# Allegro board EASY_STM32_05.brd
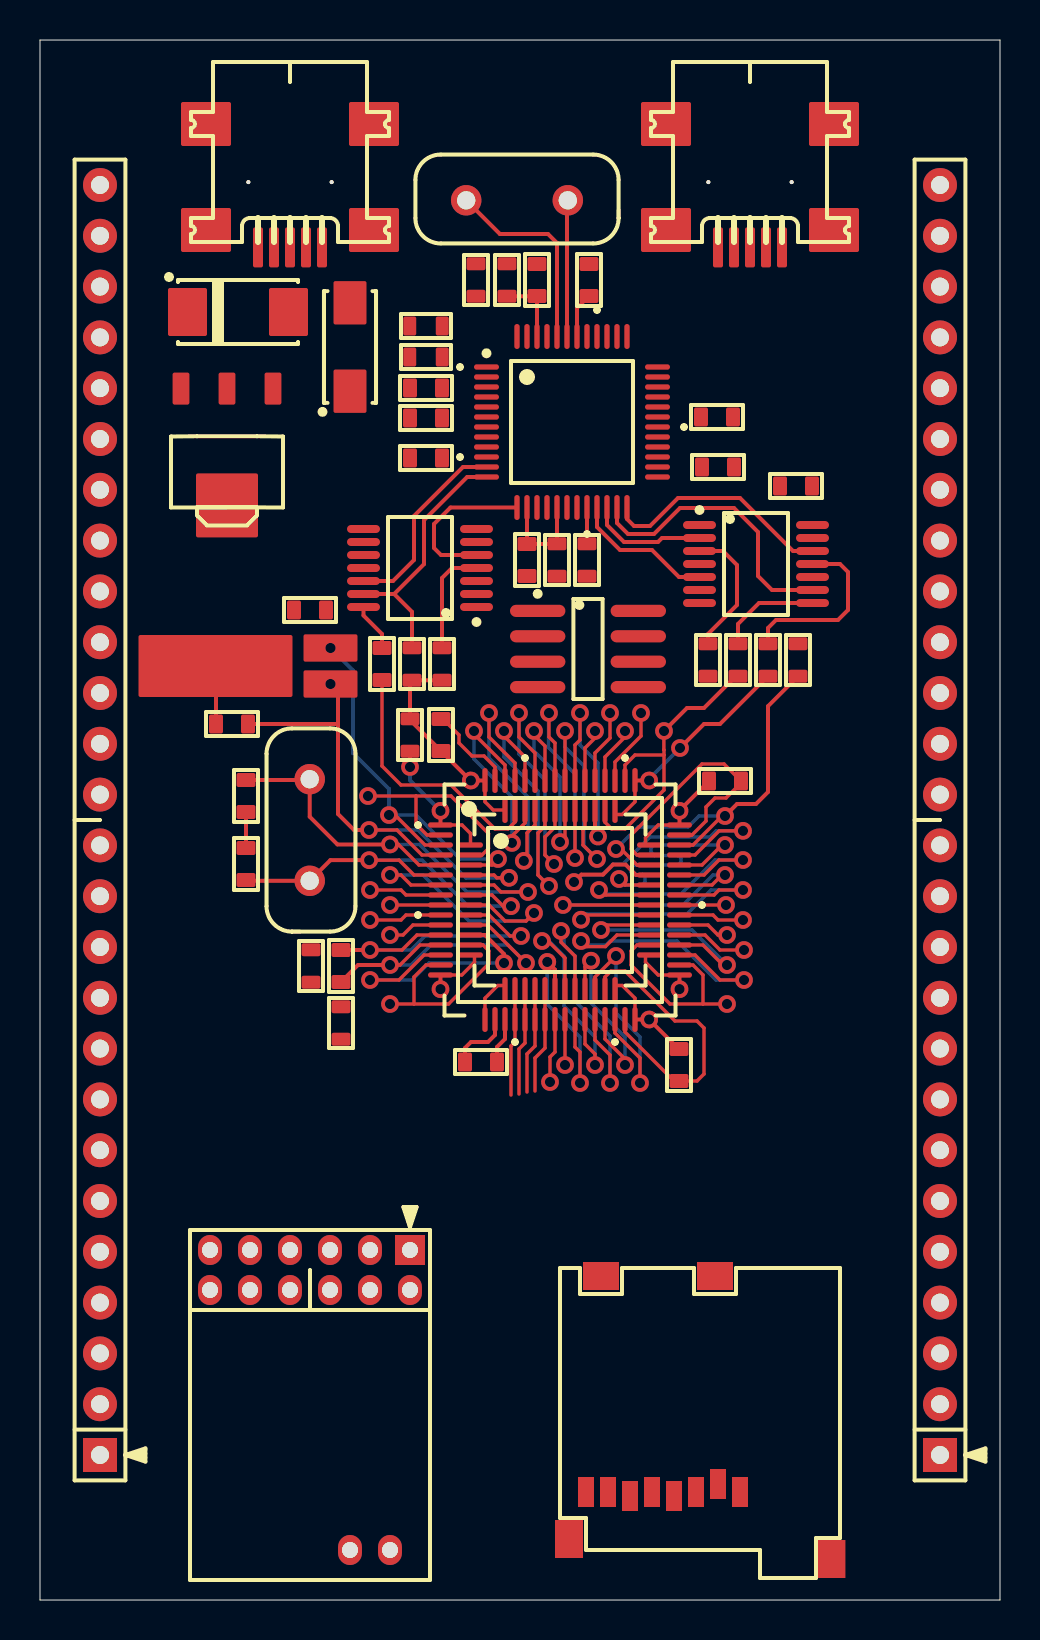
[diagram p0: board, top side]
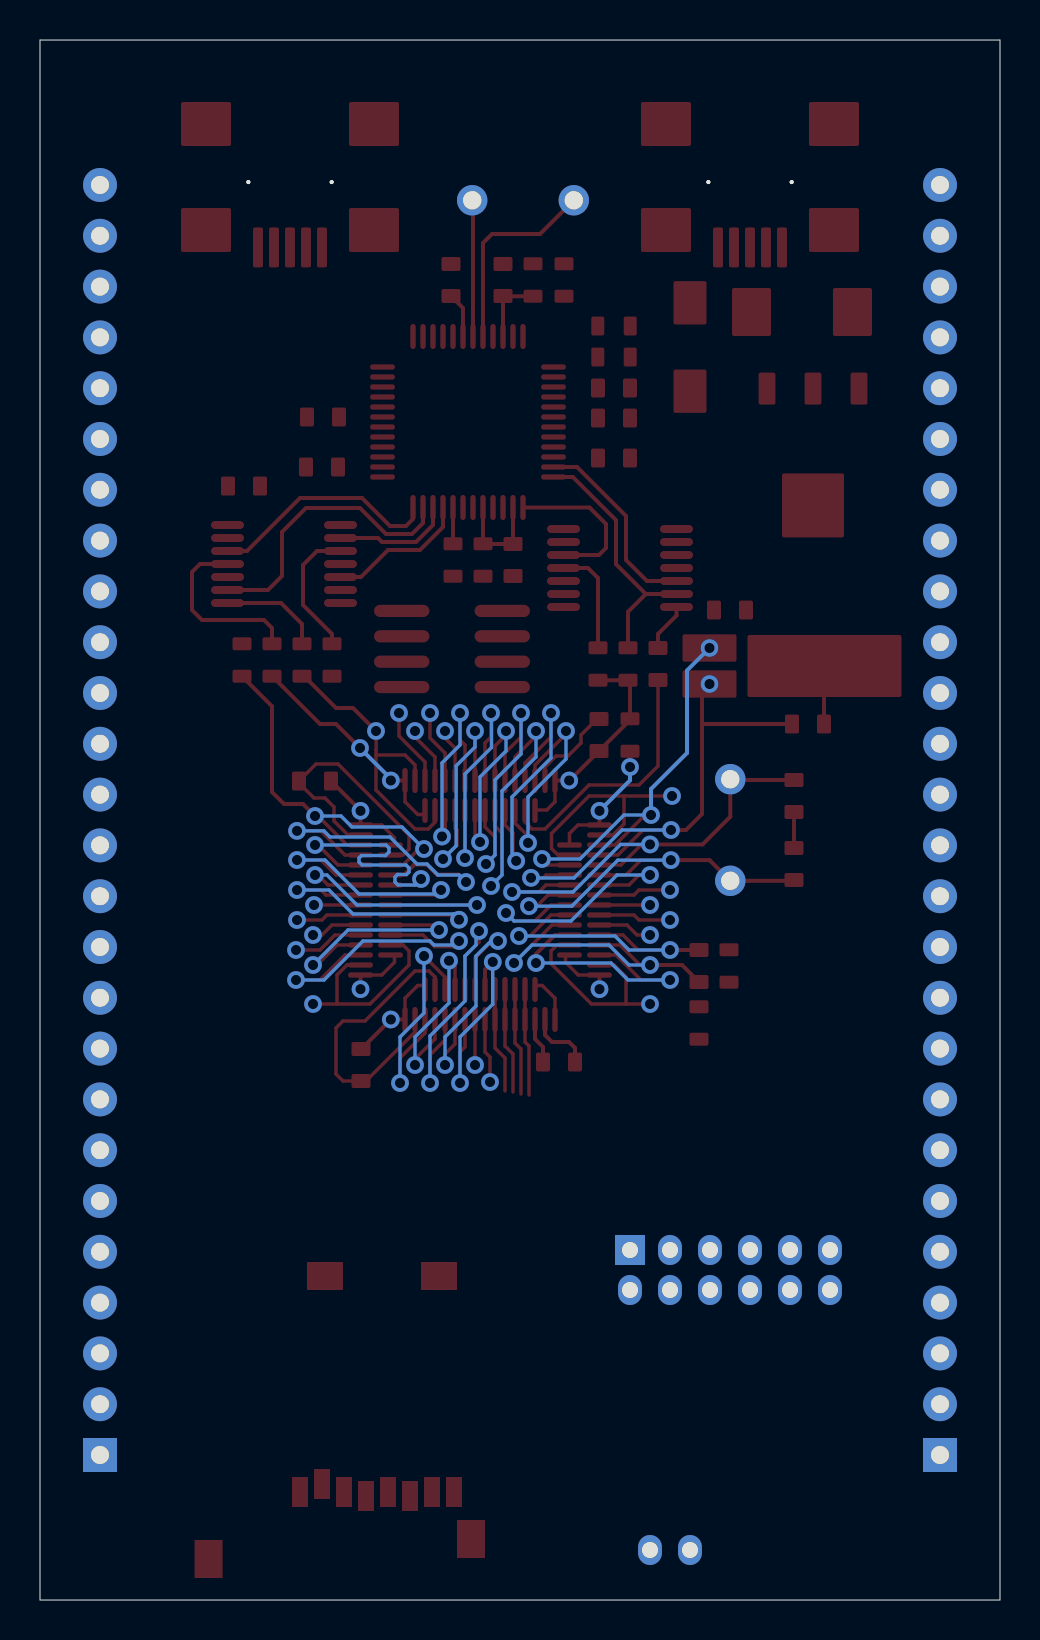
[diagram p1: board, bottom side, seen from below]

Outline 48 x 78 mm; copper layers: TOP, BOTTOM. Coordinates in mm from the lower left corner of the outline.
Outline path: 0,78 0,0 48,0 48,78 0,78

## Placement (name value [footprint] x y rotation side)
C1  22pF  [CAP0603_B]  10.3 40.2 270 top
C2  22p  [CAP0603_B]  10.3 36.8 90 top
C3  15p  [CAP0603_B]  9.6 43.8 180 top
C4  15p  [CAP0603_B]  13.5 49.5 180 top
C5  100n  [CAP0603_B]  15.05 31.7 90 top
C6  100n  [CAP0603_B]  31.95 26.75 270 top
C7  100n  [CAP0603_B]  34.25 40.95 0 top
C8  100n  [CAP0603_B]  20.05 43.25 90 top
C9  100n  [CAP0603_B]  22.05 26.9 180 top
C11  100n  [CAP0603_B]  19.3 60.6 180 top
C12  100n  [CAP0603_B]  27.45 66 90 top
C14  100n  [CAP0603_B]  19.3 57.1 180 top
C15  100n  [CAP0603_B]  24.35 52 270 top
C16  100n  [CAP0603_B]  33.9 56.65 0 top
C17  100n  [CAP0603_B]  33.85 59.15 0 top
C18  100n  [CAP0603_B]  24.85 66 90 top
C19  100n  [CAP0603_B]  19.3 59.1 180 top
C23  220uF  [CAP220UF]  9.9 64.4 0 top
C45  100nF  [CAP0603_B]  37.8 55.7 180 top
C46  100nF  [CAP0603_B]  17.1 46.8 270 top
D2  1N5819  [SS14]  15.5 62.65 90 top
J1  USB_MB  [HIROSE-US60-MB-5ST]  12.5 76.9 180 top
J*  USB_MB  [unnamed#2]  35.5 76.9 180 top
NOREF  -  []  0 -2 0 top
NOREF#2  -  []  50 0 90 top
R1  0R  [RES0603_B]  18.5 43.25 90 top
R2  0R  [RES0603_B]  15.05 28.85 270 top
R3  0R  [RES0603_B]  13.55 31.7 270 top
R4  470R  [RES0603_B]  23.35 66 270 top
R5  4K7  [RES0603_B]  19.3 63.7 0 top
R6  10K  [RES0603_B]  19.3 62.15 180 top
R7  10K  [RES0603_B]  27.35 52 270 top
R13  1K5  [RES0603_B]  21.8 66 90 top
R14  100K  [RES0603_B]  25.85 52 270 top
R35  100R  [RES0603_B]  33.4 47 270 top
R36  100R  [RES0603_B]  37.9 47 270 top
R37  100R  [RES0603_B]  34.9 47 270 top
R38  100R  [RES0603_B]  36.4 47 270 top
R39  100K  [RES0603_B]  18.6 46.8 90 top
R40  100K  [RES0603_B]  20.1 46.8 90 top
REF  val  [unnamed#3]  45 7.25 90 top
REF#2  val  [unnamed#4]  18.5 17.5 180 top
U1  STM32F103RCT6  [LQFP64_MODIFIED]  26 35 0 top
U2  STM32F100  [LQFP48L_MODIFIED]  26 35 0 top
U3  FT2232D  [LQFP48L]  26.6 58.9 0 top
U4  AT93C46-10SI-2.7  [SOIC8S1JEDECM]  27.4 47.55 270 top
U5  74LVC125A  [TSOP65P640X120-14]  35.8 51.8 270 top
U6  74LVC125A  [TSOP65P640X120-14]  19 51.6 90 top
U7  LD1117-3V3  [SOT-223]  9.35 57.38 180 top
U10  MICRO_SD  [MICRO_SD_PUSH]  40 16.6 180 top
UNK*  val  [unnamed#3]  3 7.25 90 top
Y1  8M  [XTAL_DIP]  13.49 35.96 90 top
Y2  32.768KHz  [RTC-CRYSTAL]  10.53 46.7 90 top
Y3  6M  [XTAL_DIP]  26.39 69.99 180 top

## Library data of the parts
C1-C9 = C1005_0: User Part Number: pn; Tolerance: RichardLC
C11 C12 C14-C19 = CAP NP_0: User Part Number: pn; Tolerance: RichardLC
C23 = CAPACITOR POL: User Part Number: pn; Tolerance: RichardLC
C45 C46 = C1005_5: User Part Number: pn; Tolerance: RichardLC
D2 = DIODE SCHOTTKY_1: User Part Number: pn; Tolerance: RichardLC
J1 = CON9: User Part Number: pn; Tolerance: RichardLC
J* UNK* = -: Tolerance: RichardLC; User Part Number: pn
R1-R7 R13 R14 R35-R40 = R_0: User Part Number: pn; Tolerance: RichardLC
REF REF#2 = -: User Part Number: pn; Tolerance: RichardLC
U1 = STM32F103RCT6_2: User Part Number: pn; Tolerance: RichardLC
U2 = STM32F100_1: User Part Number: pn; Tolerance: RichardLC
U3 = FT2232D_0: User Part Number: pn; Tolerance: RichardLC
U4 = 93C46_2: User Part Number: pn; Tolerance: RichardLC
U5 U6 = 74HC125/LCC_0: User Part Number: pn; Tolerance: RichardLC
U7 = LD1117: User Part Number: pn; Tolerance: RichardLC
U10 = MOLEX_uSD_0: User Part Number: pn; Tolerance: RichardLC
Y1 Y3 = ZTB: Tolerance: ***; User Part Number: ***
Y2 = ZTA_0: User Part Number: pn; Tolerance: RichardLC

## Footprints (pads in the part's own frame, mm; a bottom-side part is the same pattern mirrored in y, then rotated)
CAP220UF
  custom 0.487x0.487 smd: 1(-2.525,0) 2(2.525,0)
CAP0603_B
  custom 0.175x0.175 smd: 1(-0.8,0) 2(0.8,0)
HIROSE-US60-MB-5ST
  round 0.2 hole 0.9 unplated: (-2.083,6.005) (2.083,6.005)
  custom 0.125x0.125 smd: 1(-1.6,9.271) 2(-0.8,9.271) 3(0,9.271) 4(0.8,9.271) 5(1.6,9.271)
  custom 0.55x0.55 smd: 6(-4.2,3.1) 7(4.2,3.1) 8(-4.2,8.4) 9(4.2,8.4)
LQFP48L
  oval 1.25x0.27 smd: 1(-4.275,2.75) 2(-4.275,2.25) 3(-4.275,1.75) 4(-4.275,1.25) 5(-4.275,0.75) 6(-4.275,0.25) 7(-4.275,-0.25) 8(-4.275,-0.75) 9(-4.275,-1.25) 10(-4.275,-1.75) 11(-4.275,-2.25) 12(-4.275,-2.75) 25(4.275,-2.75) 26(4.275,-2.25) 27(4.275,-1.75) 28(4.275,-1.25) 29(4.275,-0.75) 30(4.275,-0.25) 31(4.275,0.25) 32(4.275,0.75) 33(4.275,1.25) 34(4.275,1.75) 35(4.275,2.25) 36(4.275,2.75)
  oval 0.27x1.25 smd: 13(-2.75,-4.275) 14(-2.25,-4.275) 15(-1.75,-4.275) 16(-1.25,-4.275) 17(-0.75,-4.275) 18(-0.25,-4.275) 19(0.25,-4.275) 20(0.75,-4.275) 21(1.25,-4.275) 22(1.75,-4.275) 23(2.25,-4.275) 24(2.75,-4.275) 37(2.75,4.275) 38(2.25,4.275) 39(1.75,4.275) 40(1.25,4.275) 41(0.75,4.275) 42(0.25,4.275) 43(-0.25,4.275) 44(-0.75,4.275) 45(-1.25,4.275) 46(-1.75,4.275) 47(-2.25,4.275) 48(-2.75,4.275)
LQFP48L_MODIFIED
  oval 1.25x0.27 smd: 1(-4.475,2.75) 2(-4.475,2.25) 3(-4.475,1.75) 4(-4.475,1.25) 5(-4.475,0.75) 6(-4.475,0.25) 7(-4.475,-0.25) 8(-4.475,-0.75) 9(-4.475,-1.25) 10(-4.475,-1.75) 11(-4.475,-2.25) 12(-4.475,-2.75) 25(4.475,-2.75) 26(4.475,-2.25) 27(4.475,-1.75) 28(4.475,-1.25) 29(4.475,-0.75) 30(4.475,-0.25) 31(4.475,0.25) 32(4.475,0.75) 33(4.475,1.25) 34(4.475,1.75) 35(4.475,2.25) 36(4.475,2.75)
  oval 0.27x1.25 smd: 13(-2.75,-4.475) 14(-2.25,-4.475) 15(-1.75,-4.475) 16(-1.25,-4.475) 17(-0.75,-4.475) 18(-0.25,-4.475) 19(0.25,-4.475) 20(0.75,-4.475) 21(1.25,-4.475) 22(1.75,-4.475) 23(2.25,-4.475) 24(2.75,-4.475) 37(2.75,4.475) 38(2.25,4.475) 39(1.75,4.475) 40(1.25,4.475) 41(0.75,4.475) 42(0.25,4.475) 43(-0.25,4.475) 44(-0.75,4.475) 45(-1.25,4.475) 46(-1.75,4.475) 47(-2.25,4.475) 48(-2.75,4.475)
LQFP64_MODIFIED
  oval 1.25x0.27 smd: 1(-5.975,3.75) 2(-5.975,3.25) 3(-5.975,2.75) 4(-5.975,2.25) 5(-5.975,1.75) 6(-5.975,1.25) 7(-5.975,0.75) 8(-5.975,0.25) 9(-5.975,-0.25) 10(-5.975,-0.75) 11(-5.975,-1.25) 12(-5.975,-1.75) 13(-5.975,-2.25) 14(-5.975,-2.75) 15(-5.975,-3.25) 16(-5.975,-3.75) 33(5.975,-3.75) 34(5.975,-3.25) 35(5.975,-2.75) 36(5.975,-2.25) 37(5.975,-1.75) 38(5.975,-1.25) 39(5.975,-0.75) 40(5.975,-0.25) 41(5.975,0.25) 42(5.975,0.75) 43(5.975,1.25) 44(5.975,1.75) 45(5.975,2.25) 46(5.975,2.75) 47(5.975,3.25) 48(5.975,3.75)
  oval 0.27x1.25 smd: 17(-3.75,-5.975) 18(-3.25,-5.975) 19(-2.75,-5.975) 20(-2.25,-5.975) 21(-1.75,-5.975) 22(-1.25,-5.975) 23(-0.75,-5.975) 24(-0.25,-5.975) 25(0.25,-5.975) 26(0.75,-5.975) 27(1.25,-5.975) 28(1.75,-5.975) 29(2.25,-5.975) 30(2.75,-5.975) 31(3.25,-5.975) 32(3.75,-5.975) 49(3.75,5.975) 50(3.25,5.975) 51(2.75,5.975) 52(2.25,5.975) 53(1.75,5.975) 54(1.25,5.975) 55(0.75,5.975) 56(0.25,5.975) 57(-0.25,5.975) 58(-0.75,5.975) 59(-1.25,5.975) 60(-1.75,5.975) 61(-2.25,5.975) 62(-2.75,5.975) 63(-3.25,5.975) 64(-3.75,5.975)
MICRO_SD_PUSH
  rect 0.8x1.5 smd: 1(5,11.2) 2(6.1,10.8) 3(7.2,11.2) 4(8.3,11.4) 5(9.4,11.2) 6(10.5,11.4) 7(11.6,11.2) 8(12.7,11.2)
  rect 1.4x1.9 smd: G1(0.43,14.55) G2(13.55,13.55)
  rect 1.8x1.4 smd: S1(6.25,0.4) S2(11.95,0.4)
RES0603_B
  custom 0.163x0.163 smd: 1(-0.812,0) 2(0.812,0)
RTC-CRYSTAL
  custom 0.343x0.343 smd: 1(-0.9,-4) 2(0.9,-4)
  custom 0.775x0.775 smd: 3(0,1.75)
SOIC8S1JEDECM
  oval 0.61x2.77 smd: 1(-1.905,-2.515) 2(-0.635,-2.515) 3(0.635,-2.515) 4(1.905,-2.515) 5(1.905,2.515) 6(0.635,2.515) 7(-0.635,2.515) 8(-1.905,2.515)
SOT-223
  custom 0.21x0.21 smd: 1(-2.3,-3.195) 2(0,-3.195) 3(2.3,-3.195)
  custom 0.775x0.775 smd: 4(0,2.645)
SS14
  custom 0.412x0.412 smd: A(2.21,0) C(-2.21,0)
TSOP65P640X120-14
  oval 0.4x1.65 smd: 1(-1.95,-2.825) 2(-1.3,-2.825) 3(-0.65,-2.825) 4(0,-2.825) 5(0.65,-2.825) 6(1.3,-2.825) 7(1.95,-2.825) 8(1.95,2.825) 9(1.3,2.825) 10(0.65,2.825) 11(0,2.825) 12(-0.65,2.825) 13(-1.3,2.825) 14(-1.95,2.825)
unnamed#2
  round 0.2 hole 0.9 unplated: (-2.083,6.005) (2.083,6.005)
  custom 0.125x0.125 smd: 1(-1.6,9.271) 2(-0.8,9.271) 3(0,9.271) 4(0.8,9.271) 5(1.6,9.271)
  custom 0.55x0.55 smd: 6(-4.2,3.1) 7(4.2,3.1) 8(-4.2,8.4) 9(4.2,8.4)
unnamed#3
  rect 1.7x1.7 hole 0.9: 1(0,0)
  round 1.7 hole 0.9: 2(2.54,0) 3(5.08,0) 4(7.62,0) 5(10.16,0) 6(12.7,0) 7(15.24,0) 8(17.78,0) 9(20.32,0) 10(22.86,0) 11(25.4,0) 12(27.94,0) 13(30.48,0) 14(33.02,0) 15(35.56,0) 16(38.1,0) 17(40.64,0) 18(43.18,0) 19(45.72,0) 20(48.26,0) 21(50.8,0) 22(53.34,0) 23(55.88,0) 24(58.42,0) 25(60.96,0) 26(63.5,0)
unnamed#4
  rect 1.5x1.5 hole 0.8: 1(0,0)
  oval 1.194x1.499 hole 0.8: 2(0,2) 3(2,0) 4(2,2) 5(4,0) 6(4,2) 7(6,0) 8(6,2) 9(8,0) 10(8,2) 11(10,0) 12(10,2) 13(1,15) 14(3,15)
XTAL_DIP
  round 1.524 hole 0.914: 1(0,0) 2(5.08,0)

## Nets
+3V3: C6.1 C7.1 C8.1 C9.1 C14.1 C15.1 C16.1 C17.1 C45.1 C46.1 R1.2 R2.2 R14.1 R39.1 R40.1 U1.19(VDD_4) U1.32(VDD_1) U1.48(VDD_2) U1.64(VDD_3) U2.24(VDD_1) U2.36(VDD_2) U2.48(VDD_3) U3.10(SI/WUA) U3.14(VCCIOA) U3.17(ADBUS6) U3.26(SI/WUB) U3.31(VCCIOB) U5.14(VCC) U6.14(VCC) U7.2(VOUT) U7.4(SH) U10.4(VDD)
+5V: C11.1 C12.1 C23.1 D2.C R4.1 U3.3(VCC1) U3.42(VCC2) U4.8(VCC) U7.3(VIN)
GND: C1.2 C2.2 C3.2 C4.2 C6.2 C7.2 C8.2 C9.2 C11.2 C12.2 C14.2 C15.2 C16.2 C17.2 C18.2 C19.2 C23.2 C45.2 C46.2 J1.5 J1.6 J1.7 J1.8 J1.9 R3.2 R6.2 R7.2 R14.2 U1.18(VSS_4) U1.31(VSS_1) U1.47(VSS_2) U1.63(VSS_3) U2.23(VSS_1) U2.35(VSS_2) U2.47(VSS_3) U3.9(GND1) U3.18(GND2) U3.25(GND3) U3.34(GND4) U3.45(AGND) U3.47(TEST) U4.5(GND) U4.7(NC) U5.7(GND) U6.1(O\E\1\) U6.2(A1) U6.7(GND) U6.9(A3) U6.10(O\E\3\) U7.1(GND) U10.6(VSS) Y2.3
VBAT: R1.1 U1.1(VBAT) U2.1(VBAT)
VDDA: C5.1 R2.1 U1.13(VDDA) U2.9(VDDA)
VSSA: C5.2 R3.1 U1.12(VSSA) U2.8(VSSA)
BOOT0: U1.60(BOOT0) U2.44(BOOT0)
EECK: U3.1(EESK) U4.2(CLK)
EECS: U3.48(EECS) U4.1(CS)
EEDA: U3.2(EEDATA) U4.3(DI)
JT_SRSTN: U3.16(ADBUS7)
JTG_SELN: U5.1(O\E\1\) U5.4(O\E\2\) U5.10(O\E\3\) U5.13(O\E\4\)
NRST: U1.7(NRST) U2.7(NRST)
OSC32_IN: C4.1 U1.3(PC14/OSC32_IN) U2.3(PC14/OSC32_IN) Y2.2
OSC32_OUT: C3.1 U1.4(PC15/OSC32/OUT) U2.4(PC15/OSC32_OUT) Y2.1
OSC_IN: C1.1 U1.5(PD0/OSC_IN) U2.5(PD0/OSC_IN) Y1.2
OSC_OUT: C2.1 U1.6(PD1/OSC_OUT) U2.6(PD1/OSC_OUT) Y1.1
PA0: U1.14(PA0-WKUP) U2.10(PA0/WKUP)
PA1: U1.15(PA1) U2.11(PA1)
PA2: U1.16(PA2) U2.12(PA2)
PA3: U1.17(PA3) U2.13(PA3)
PA4: U1.20(PA4) U2.14(PA4)
PA5: U1.21(PA5) U2.15(PA5)
PA6: U1.22(PA6) U2.16(PA6)
PA7: U1.23(PA7) U2.17(PA7)
PA8: U1.41(PA8) U2.29(PA8)
PA9: U1.42(PA9) U2.30(PA9)
PA10: U1.43(PA10) U2.31(PA10)
PA11: U1.44(PA11) U2.32(PA11)
PA12: U1.45(PA12) U2.33(PA12)
PA13: R36.2 U1.46(PA13) U2.34(PA13)
PA14: R38.2 U1.49(PA14) U2.37(PA14)
PA15: R37.2 U1.50(PA15) U2.38(PA15)
PB0: U1.26(PB0) U2.18(PB0)
PB1: U1.27(PB1) U2.19(PB1)
PB2: U1.28(PB2/BOOT1) U2.20(PB2)
PB3: R35.2 U1.55(PB3) U2.39(PB3)
PB4: U1.56(PB4) U2.40(PB4)
PB5: U1.57(PB5) U2.41(PB5)
PB6: U1.58(PB6) U2.42(PB6)
PB7: U1.59(PB7) U2.43(PB7)
PB8: U1.61(PB8) U2.45(PB8)
PB9: U1.62(PB9) U2.46(PB9)
PB10: U1.29(PB10) U2.21(PB10)
PB11: U1.30(PB11) U2.22(PB11)
PB12: U1.33(PB12) U2.25(PB12)
PB13: U1.34(PB13) U2.26(PB13)
PB14: U1.35(PB14) U2.27(PB14)
PB15: U1.36(PB15) U2.28(PB15)
PC0: U1.8(PC0)
PC1: U1.9(PC1)
PC2: U1.10(PC2)
PC3: U1.11(PC3)
PC4: U1.24(PC4)
PC5: U1.25(PC5)
PC6: U1.37(PC6)
PC7: U1.38(PC7)
PC8: U1.39(PC8)
PC9: U1.40(PC9)
PC10: U1.51(PC10)
PC11: U1.52(PC11)
PC12: U1.53(PC12)
PC13: U1.2(PC13/TAMPER/RTC) U2.2(PC13/TAMPER/RTC)
PD2: U1.54(PD2)
RXD: U3.39(BDBUS1)
SRST: U3.11(ACBUS3) U6.12(A4)
SRST_OE: R39.2 U3.12(ACBUS2) U6.13(O\E\4\)
TRST: U3.13(ACBUS1) U6.5(A2)
TRST_OE: R40.2 U3.15(ACBUS0) U6.4(O\E\2\)
TXD: U3.40(BDBUS0)
USB_CLK: U3.24(ADBUS0) U5.12(A4)
USB_TDI: U3.23(ADBUS1) U5.9(A3)
USB_TDO: U3.22(ADBUS2) U5.2(A1)
USB_TMS: U3.21(ADBUS3) U5.5(A2)
N50123: J1.3 R13.1 U3.7(USBDP)
N50127: C18.1 R4.2 U3.46(AVCC)
N50535: R7.1 U3.20(ADBUS4)
N50793: U3.43(XTIN) Y3.1
N50801: U3.44(XTOUT) Y3.2
N51025: J1.1
N51029: D2.A R5.1
N51319: R13.2 U3.5(R\S\T\O\U\T\)
N51335: J1.2 U3.8(USBDM)
N51347: R5.2 R6.1 U3.4(R\E\S\E\T\)
N51363: C19.1 U3.6(3V3OUT)
N51511: U4.4(DO)
N70187: U10.7(DAT0/DO)
N70219: U10.5(CLK)
N70227: U10.2(CD/C\S\/DAT3)
N70305: U10.S2
N70345: U10.G2
N70603: U10.8(DAT1/RSV)
N14914218: U10.3(CMD/DI)
N14919452: R35.1 U5.3(Y1)
N14919456: R36.1 U5.6(Y2)
N14919460: R37.1 U5.8(Y3)
N14919464: R38.1 U5.11(Y4)
N14919761: U10.1(DAT2/NC)
N14928576: U6.6(Y2)
N14928580: U6.11(Y4)

Pads without a net: J1 4; J* 1 2 3 4 5 6 7 8 9; REF 1 2 3 4 5 6 7 8 9 10 11 12 13 14 15 16 17 18 19 20 21 22 23 24 25 26; REF#2 1 2 3 4 5 6 7 8 9 10 11 12 13 14; U3 19 27 28 29 30 32 33 35 36 37 38 41; U4 6; U6 3 8; U10 G1 S1; UNK* 1 2 3 4 5 6 7 8 9 10 11 12 13 14 15 16 17 18 19 20 21 22 23 24 25 26

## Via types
v1: diameter 0.889, hole 0.508, TOP to BOTTOM, 87 vias

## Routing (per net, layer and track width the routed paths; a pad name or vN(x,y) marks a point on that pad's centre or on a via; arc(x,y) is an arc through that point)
+3V3: length 30.9
  TOP w0.175: U1.48 30.91,38.75 30.27,38.11 30.27,37.75 ; U1.32 29.75,30.09 29.11,30.73 28.75,30.73 ; 23.25,39.5 22.66,39.5 22.25,39.91 U1.64
  TOP w0.2: U1.64 v1(21.54,40.98) 21.52,40.98 C8.1 18.5,44 R1.2 18.5,45.89 R39.1 R40.1 ; U3.17 R14.1 25.84,52.8 C15.1 U3.14 ; 31.93,27.55 v1(30.46,29.02) U1.32 ; C9.1 22.85,27.65 23.25,28.05 U1.19 ; C46.1 17.1,48.3 16.18,49.23 U6.14 ; C7.1 31.98,39.48 v1(31.98,39.46) U1.48
+5V: length 2.3
  TOP w0.2: 26.85,63.17 26.85,64.6 C12.1
GND: length 54
  TOP w0.175: 28.25,30.73 28.25,31.15 28.55,31.45 29.25,31.45 31.75,28.95 32.85,28.95 33.2,28.6 33.2,26.3 32.85,25.95 C6.2 31.7,25.95 29.25,28.4 U1.31 ; U2.35 29.85,37.25 29.55,37.55 29.55,38.25 33.1,41.8 34.2,41.8 C7.2 35.05,40.85 34.3,40.1 33.75,40.1 33.3,39.65 33.3,38.95 32.6,38.25 U1.47 ; C46.2 17.1,41.7 18.05,40.75 20.55,40.75 22.75,38.55 23.4,38.55 23.75,38.9 U2.47 ; U1.63 22.75,41.65 22.2,42.2 21.6,42.2 20.95,42.85 20.95,43.25 20.15,44.05 C8.2
  TOP w0.2: C9.2 21.25,27.6 21.55,27.9 22.4,27.9 22.75,28.25 U1.18 ; Y2.3 8.8,46.67 C3.2 ; C2.2 C1.2
VBAT: length 6.6
  TOP w0.175: U1.1 21.1,38.75 21.52,38.33 U2.1
  TOP w0.2: U1.1 v1(20.02,39.46) ; R1.1 v1(18.5,41.65)
  BOTTOM w0.2: v1(20.02,39.46) 18.5,40.98 v1(18.5,41.65)
VDDA: length 16.9
  TOP w0.175: v1(17.5,31.75) 18,31.75 19,32.75 U1.13 ; U2.9 22.4,33.75 v1(24.3,31.85)
  TOP w0.2: C5.1 15.9,31.75 v1(17.5,31.75)
  BOTTOM w0.175: v1(24.3,31.85) 23.4,32.75 19.55,32.75 18.55,31.75 v1(17.5,31.75)
VSSA: length 16.1
  TOP w0.175: U2.8 22.45,34.25 23.5,33.2 v1(24.05,33.2) ; U1.12 18.85,33.25 18.1,32.5 v1(16.5,32.5)
  TOP w0.2: v1(16.5,32.5) C5.2
  BOTTOM w0.175: v1(24.05,33.2) 19.25,33.2 18.55,32.5 v1(16.5,32.5)
BOOT0: length 15.7
  TOP w0.175: v1(25.45,35.7) 24.9,36.25 24.9,38.35 25.25,38.7 U2.44 ; v1(23.2,43.45) 23.2,43.2 24.25,42.15 U1.60
  BOTTOM w0.175: v1(23.2,43.45) 23.2,42.15 24.9,40.45 24.9,36.25 v1(25.45,35.7)
NRST: length 14.7
  TOP w0.175: U1.7 18.55,35.75 18.05,36.25 v1(17.5,36.25) ; U2.7 22.45,34.75 23.25,33.95 24.3,33.95 v1(24.7,34.35)
  BOTTOM w0.175: v1(24.7,34.35) 24.3,33.95 21.45,33.95 19.15,36.25 v1(17.5,36.25)
OSC32_IN: length 20.6
  TOP w0.175: U2.3 22.6,36.75 v1(22.9,37.05) ; v1(17.45,39.25) 17.75,39.25 19.25,37.75 U1.3
  BOTTOM w0.175: v1(17.45,39.25) 18.8,39.25 21,37.05 v1(22.9,37.05)
  BOTTOM w0.2: v1(17.45,39.25) 17.45,40.55 15.65,42.35 15.65,46.48 v1(14.53,47.6)
OSC32_OUT: length 27.1
  TOP w0.175: v1(16.45,38.5) 17.85,38.5 19.1,37.25 U1.4 ; v1(23.45,36.11) 22.84,36.11 22.7,36.25 U2.4
  TOP w0.2: v1(14.53,45.8) 14.9,45.42 14.9,43.8 ; 14.9,43.8 14.9,39.3 15.7,38.5 v1(16.45,38.5) ; 14.9,43.8 C3.1
  BOTTOM w0.175: v1(16.45,38.5) 18.9,38.5 21.3,36.1 23.44,36.1 v1(23.45,36.11)
OSC_IN: length 23.5
  TOP w0.175: v1(24.4,35.4) 23.05,35.4 22.7,35.75 U2.5 ; v1(17.5,37.78) 17.92,37.78 18.95,36.75 U1.5
  TOP w0.2: C1.1 13.45,41 Y1.2 13.49,39.16 14.87,37.78 v1(17.5,37.78)
  BOTTOM w0.175: v1(24.4,35.4) 21.35,35.4 18.97,37.78 v1(17.5,37.78)
OSC_OUT: length 20.8
  TOP w0.175: U1.6 18.7,36.25 17.96,36.99 v1(16.46,36.99) ; v1(23.55,34.69) 23.16,34.69 22.6,35.25 U2.6
  TOP w0.2: C2.1 10.34,35.96 Y1.1 14.52,36.99 v1(16.46,36.99)
  BOTTOM w0.175: v1(23.55,34.69) 21.41,34.69 19.11,36.99 v1(16.46,36.99)
PA0: length 13.6
  TOP w0.175: v1(16.5,31) 17.95,31 19.2,32.25 U1.14
  TOP w0.2: U2.10 22.25,33.25 23.2,32.3 v1(23.2,31.85)
  BOTTOM w0.175: v1(23.2,31.85) 19.45,31.85 18.6,31 v1(16.5,31)
PA1: length 10.2
  TOP w0.175: U1.15 19.3,31.75 18.7,31.15 18.7,29.8 ; v1(17.5,29.8) 18.7,29.8 ; 18.7,29.8 20.43,29.8 22.45,31.82 22.45,32.45 22.15,32.75 21.73,32.75
PA2: length 3
  TOP w0.175: 21.73,32.25 21.73,31.89 21.09,31.25 U1.16
  TOP w0.2: U1.16 v1(20.02,30.54)
PA3: length 2.3
  TOP w0.175: U1.17 22.25,30.09 22.89,30.73 23.25,30.73
PA4: length 5.6
  TOP w0.175: 23.75,30.73 U2.14 U1.20 23.75,27.9 23.55,27.7 23.55,25.25
PA5: length 5.5
  TOP w0.175: 23.95,25.3 23.95,27.55 24.25,27.85 U1.21 U2.15 24.25,30.73
PA6: length 5.5
  TOP w0.175: 24.75,30.73 U2.16 U1.22 24.75,27.7 24.35,27.3 24.35,25.4
PA7: length 5.5
  TOP w0.175: 24.75,25.45 24.75,27.1 25.25,27.6 U1.23 U2.17 25.25,30.73
PA8: length 15.5
  TOP w0.175: v1(35.15,35.5) 33.95,35.5 33.7,35.25 U1.41 ; v1(27.05,34.01) 27.06,34.01 27.3,34.25 U2.29
  BOTTOM w0.175: v1(27.05,34.01) 27.34,34.3 32.35,34.3 33.55,35.5 v1(35.15,35.5)
PA9: length 15.5
  TOP w0.175: v1(26.15,34.75) U2.30 ; U1.42 33.6,35.75 34.1,36.25 v1(34.25,36.25)
  BOTTOM w0.175: v1(34.25,36.25) 33.65,36.25 32.15,34.75 v1(26.15,34.75)
PA10: length 14.1
  TOP w0.175: U2.31 28.3,35.25 28.05,35.5 v1(27.95,35.5) ; U1.43 33.2,36.25 33.95,37 v1(35.15,37)
  BOTTOM w0.175: v1(35.15,37) 33.75,37 32.05,35.3 28.15,35.3 v1(27.95,35.5)
PA11: length 15.5
  TOP w0.175: U1.44 33.1,36.75 34.1,37.75 v1(34.25,37.75) ; U2.32 29.25,35.75 v1(28.95,36.05)
  BOTTOM w0.175: v1(34.25,37.75) 30.7,37.75 30.55,37.6 30.55,37.4 30.73,37.23 31.93,37.23 32.05,37.1 32.05,36.9 31.9,36.75 29.7,36.75 29.55,36.6 29.55,36.4 29.68,36.27 30.12,36.27 30.25,36.15 30.25,35.9 30.1,35.75 29.25,35.75 v1(28.95,36.05)
PA12: length 17.5
  TOP w0.175: U1.45 32.75,37.25 33.96,38.46 v1(35.15,38.46)
  TOP w0.2: U2.33 29.8,36.25 29.28,36.77 28.65,36.77 28.15,36.27 27.07,36.27 v1(26.7,35.9)
  BOTTOM w0.175: v1(35.15,38.46) 33.81,38.46 33.5,38.15 30.5,38.15 29.15,36.8 28.65,36.8 28.1,36.25 27.05,36.25 v1(26.7,35.9)
PA13: length 20.1
  TOP w0.175: v1(28.8,37.55) 29.05,37.55 29.85,36.75 U2.34 ; v1(34.25,39.2) 34.1,39.2 32.65,37.75 U1.46
  TOP w0.2: v1(34.25,39.2) 34.85,39.8 35.8,39.8 36.4,40.4 36.4,44.69 R36.2
  BOTTOM w0.175: v1(28.8,37.55) 29.9,38.65 32.4,38.65 32.95,39.2 v1(34.25,39.2)
PA14: length 11.2
  TOP w0.175: U1.49 29.75,39.91 29.11,39.27 28.75,39.27
  TOP w0.2: U1.49 v1(30.46,40.98) ; R38.2 36.39,46.19 34,43.8 33.2,43.8 v1(32,42.6)
  BOTTOM w0.2: v1(32,42.6) 30.46,41.06 v1(30.46,40.98)
PA15: length 15.2
  TOP w0.175: 31.2,42.25 31.2,42.5 31.19,42.51 31.19,43.09 31.2,43.1 v1(31.2,43.45) ; 31.2,42.25 29.75,42.25 29.25,41.75 U1.50 ; 31.2,42.25 31.2,40.5 29.25,38.55 28.59,38.55 28.25,38.89 U2.38
  TOP w0.2: v1(31.2,43.45) 32.35,44.6 33.2,44.6 34.79,46.19 R37.2
PB0: length 11.5
  TOP w0.175: U1.26 26.75,27.65 27,27.4 v1(27,25.85)
  TOP w0.2: U2.18 25.75,31.52 v1(25.36,31.9)
  BOTTOM w0.175: v1(27,25.85) 27,28.15 25.36,29.79 v1(25.36,31.9)
PB1: length 13.1
  TOP w0.175: U1.27 27.25,27.8 27.75,27.3 v1(27.75,26.75) ; v1(25.1,32.95) 25.4,32.95 26.25,32.1 U2.19
  BOTTOM w0.175: v1(27.75,26.75) 27.75,28.15 26.2,29.7 26.2,32.2 25.45,32.95 v1(25.1,32.95)
PB2: length 15.3
  TOP w0.175: U1.28 27.75,28 28.5,27.25 v1(28.5,25.85) ; v1(26.05,33.45) 26.05,32.89 26.75,32.19 U2.20
  BOTTOM w0.175: v1(28.5,25.85) 28.5,28.2 26.75,29.95 26.75,32.2 26.2,32.75 26.2,33.3 v1(26.05,33.45)
PB3: length 11.4
  TOP w0.175: v1(27,44.35) 27,43 26.75,42.75 U1.55
  TOP w0.2: v1(27.9,38.17) 27.75,38.33 U2.39
  BOTTOM w0.175: v1(27.9,38.17) 27.9,41.85 27,42.75 v1(27,44.35)
PB4: length 12.3
  TOP w0.175: v1(27.85,37.05) 27.15,37.75 27.15,38.5 27.25,38.6 U2.40 ; U1.56 v1(26.25,43.45)
  BOTTOM w0.175: v1(26.25,43.45) 26.25,42.65 27.19,41.71 27.19,37.71 v1(27.85,37.05)
PB5: length 13.7
  TOP w0.175: U2.41 v1(26.75,37.1) ; U1.57 25.75,42.85 25.45,43.15 v1(25.45,44.35)
  BOTTOM w0.175: v1(26.75,37.1) 26.75,41.3 25.43,42.62 25.43,44.33 v1(25.45,44.35)
PB6: length 10.5
  TOP w0.175: v1(24.7,43.45) 24.7,43.25 25.25,42.7 U1.58 ; U2.42 26.25,38.15 v1(26,37.9)
  BOTTOM w0.175: v1(26,37.9) 26,41.15 24.7,42.45 v1(24.7,43.45)
PB7: length 15
  TOP w0.175: U1.59 24.75,42.35 23.95,43.15 v1(23.95,44.35) ; U2.43 25.75,38.65 25.25,38.15 25.25,37.25 v1(25.7,36.8)
  BOTTOM w0.175: v1(25.7,36.8) 25.25,37.25 25.25,41 23.95,42.3 v1(23.95,44.35)
PB8: length 15
  TOP w0.175: v1(24.19,36.95) 24.35,37.11 24.35,38.35 24.75,38.75 U2.45 ; v1(22.45,44.35) 22.45,43.15 23.75,41.85 U1.61
  BOTTOM w0.175: v1(22.45,44.35) 22.45,42.1 24.4,40.15 24.4,37.16 v1(24.19,36.95)
PB9: length 11.4
  TOP w0.175: U1.62 23.25,41.75 21.7,43.3 v1(21.7,43.45) ; U2.46 24.25,38.85 23.6,38.2 v1(23.6,37.85)
  BOTTOM w0.175: v1(23.6,37.85) 23.6,40.15 21.7,42.05 v1(21.7,43.45)
PB10: length 10.2
  TOP w0.175: v1(29.25,26.75) 29.25,27.05 28.25,28.05 U1.29 ; v1(27.55,31.96) 27.25,31.66 U2.21
  BOTTOM w0.175: v1(29.25,26.75) 29.25,28.15 27.55,29.85 v1(27.55,31.96)
PB11: length 12.6
  TOP w0.175: v1(28.8,32.2) 27.75,31.15 U2.22 ; v1(30,25.85) 30,27.1 28.75,28.35 U1.30
  BOTTOM w0.175: v1(28.8,32.2) 28.8,29.35 30,28.15 v1(30,25.85)
PB12: length 3
  TOP w0.175: 30.27,32.25 30.27,31.89 30.91,31.25 U1.33
  TOP w0.2: U1.33 v1(31.98,30.54)
PB13: length 10
  TOP w0.175: U1.34 32.65,31.75 33.15,31.25 33.15,29.8 ; v1(34.35,29.8) 33.15,29.8 ; 33.15,29.8 31.5,29.8 29.55,31.75 29.55,32.45 29.85,32.75 30.27,32.75
PB14: length 16.6
  TOP w0.175: U2.27 28.85,33.25 28.27,32.67 27.33,32.67 v1(27.05,32.95) ; v1(35.2,31) 34,31 32.75,32.25 U1.35
  BOTTOM w0.175: v1(27.05,32.95) 27.25,32.75 28.3,32.75 28.5,32.95 31.85,32.95 33.8,31 v1(35.2,31)
PB15: length 12.3
  TOP w0.175: v1(28.05,33.5) 28.3,33.75 U2.28 ; v1(34.35,31.75) 34.15,31.75 33.15,32.75 U1.36
  BOTTOM w0.175: v1(34.35,31.75) 32.6,33.5 v1(28.05,33.5)
PC0: length 3.6
  TOP w0.175: U1.8 18.3,35.25 18.05,35.5 v1(16.5,35.5)
PC1: length 2.5
  TOP w0.175: U1.9 v1(17.5,34.75)
PC2: length 3.6
  TOP w0.175: v1(16.5,34) 18.05,34 18.3,34.25 U1.10
PC3: length 2.7
  TOP w0.175: v1(17.5,33.25) 18.15,33.25 18.65,33.75 U1.11
PC4: length 3.2
  TOP w0.175: U1.24 25.75,27.4 25.5,27.15 v1(25.5,25.9)
PC5: length 2.3
  TOP w0.175: U1.25 v1(26.25,26.75)
PC6: length 3.5
  TOP w0.175: U1.37 33.25,33.25 34,32.5 v1(35.2,32.5)
PC7: length 2.6
  TOP w0.175: v1(34.35,33.25) 33.9,33.25 33.4,33.75 U1.38
PC8: length 3.3
  TOP w0.175: v1(35.15,34) 33.9,34 33.65,34.25 U1.39
PC9: length 2.3
  TOP w0.175: U1.40 v1(34.3,34.75)
PC10: length 3.9
  TOP w0.175: v1(30.05,44.35) 30.05,43.2 28.75,41.9 U1.51
PC11: length 2.9
  TOP w0.175: v1(29.25,43.45) 29.25,43.15 28.25,42.15 U1.52
PC12: length 3.7
  TOP w0.175: v1(28.5,44.35) 28.5,43.1 27.75,42.35 U1.53
PC13: length 11.4
  TOP w0.175: U1.2 19.35,38.25 18.8,38.8 18.8,40.2 ; 18.8,40.2 v1(16.4,40.2) ; 18.8,40.2 20.55,40.2 22.43,38.33 22.43,37.58 22.1,37.25 U2.2
PD2: length 2.7
  TOP w0.175: v1(27.75,43.45) 27.75,43.1 27.25,42.6 U1.54
SRST: length 9.8
  TOP w0.2: U6.12 17.65,50.95 18.7,52 18.7,54.2 21.15,56.65 U3.11
SRST_OE: length 12.9
  TOP w0.2: U6.13 17.71,50.3 ; 17.71,50.3 18.6,49.41 R39.2 ; 17.71,50.3 19.2,51.79 19.2,53.99 21.36,56.15 U3.12
TRST: length 8
  TOP w0.2: U3.13 20.52,54.62 19.7,53.8 19.7,52.6 20.05,52.25 U6.5
TRST_OE: length 5.4
  TOP w0.2: U6.4 20.6,51.6 20.1,51.1 R40.2
USB_CLK: length 11.7
  TOP w0.2: U3.24 29.35,54.05 29.7,53.7 30.5,53.7 31.9,55.1 35,55.1 37.65,52.45 U5.12
USB_TDI: length 14.3
  TOP w0.2: U5.9 36.6,50.5 35.9,51.2 35.9,53.4 34.7,54.6 32,54.6 30.7,53.3 29.4,53.3 28.85,53.85 U3.23
USB_TDO: length 5.9
  TOP w0.2: U5.2 31.1,53.1 30.9,52.9 29.2,52.9 28.35,53.75 U3.22
USB_TMS: length 7.1
  TOP w0.2: U3.21 27.85,53.65 29,52.5 30.6,52.5 31.95,51.15 U5.5
N50127: length 3.5
  TOP w0.2: 24.85,63.17 C18.1 24.84,65.19 R4.2
N50535: length 1.8
  TOP w0.2: R7.1 U3.20
N50793: length 6.8
  TOP w0.2: Y3.1 26.35,69.95 26.35,63.17
N50801: length 10.1
  TOP w0.2: 25.85,63.17 25.85,67.85 25.4,68.3 23,68.3 Y3.2
N14919452: length 6.7
  TOP w0.2: R35.1 33.4,48.3 34.85,49.75 34.85,51.75 34.15,52.45 U5.3
N14919460: length 5.1
  TOP w0.2: R37.1 34.9,48.8 35.95,49.85 U5.8
N14919464: length 9
  TOP w0.2: R38.1 36.4,48.6 36.8,49 39.9,49 40.4,49.5 40.4,51.4 40,51.8 U5.11

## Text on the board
DIMENSION: FIGURE | SIZE | 0.508 | 0.8 | 0.8999 | 0.9144 | 1.0 | 2.4 | DRILL CHART: TOP to BOTTOM | ALL UNITS ARE IN MILLIMETERS | PLATED | QTY | 121 | 14 | 200 | 2 | 4
